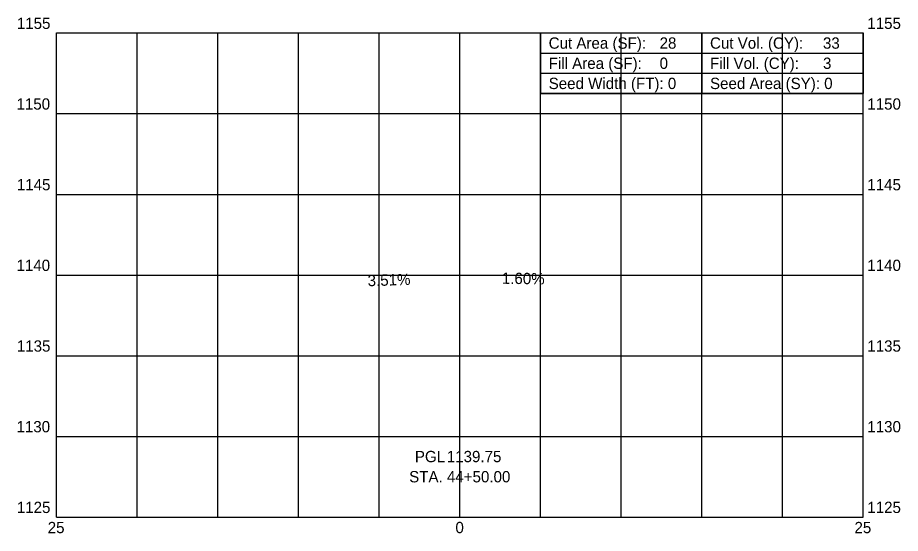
# Model space of a CAD drawing. Extents: x -27.4 to 27.3, y 1124 to 1156.
import ezdxf

# ---------------------------------------------------------------- set-up
doc = ezdxf.new("R2010")
doc.units = 0
for name, color, linetype in [('Default', 7, 'Continuous'), ('SH_Data', 7, 'Continuous'), ('SH_Major_Grid_Line', 7, 'Continuous'), ('SH_Masking', 7, 'Continuous'), ('SH_Text', 7, 'Continuous')]:
    doc.layers.add(name, color=color, linetype=linetype)

msp = doc.modelspace()

# ---------------------------------------------------------------- linework, layer by layer
at = {"layer": 'Default'}
msp.add_circle((25, 1155), 0.000417, dxfattribs=at)
msp.add_circle((25, 1155), 0.000417, dxfattribs=at)
msp.add_circle((25, 1155), 0.000417, dxfattribs=at)
msp.add_circle((25, 1155), 0.000417, dxfattribs=at)
msp.add_circle((25, 1155), 0.000417, dxfattribs=at)
msp.add_circle((25, 1155), 0.000417, dxfattribs=at)
msp.add_circle((25, 1155), 0.000417, dxfattribs=at)
msp.add_circle((25, 1155), 0.000417, dxfattribs=at)
msp.add_circle((25, 1155), 0.000417, dxfattribs=at)
msp.add_circle((25, 1155), 0.000417, dxfattribs=at)
msp.add_circle((25, 1155), 0.000417, dxfattribs=at)
msp.add_circle((25, 1155), 0.000417, dxfattribs=at)
at = {"layer": 'SH_Data'}
for p, q in [((5, 1155), (25, 1155)), ((5, 1155), (5, 1152.5)), ((15, 1155), (15, 1151.25)), ((25, 1155), (25, 1152.5)), ((5, 1153.75), (25, 1153.75)), ((5, 1152.5), (25, 1152.5)), ((13.298, 1151.875), (13.298, 1151.875)), ((22.946, 1151.875), (22.946, 1151.875))]:
    msp.add_line(p, q, dxfattribs=at)
msp.add_lwpolyline([(5, 1152.5), (5, 1151.25), (25, 1151.25), (25, 1152.5)], dxfattribs=at)
at = {"layer": 'SH_Major_Grid_Line'}
for p, q in [((-25, 1125), (-25, 1155)), ((-25, 1155), (25, 1155)), ((-20, 1125), (-20, 1155)), ((-15, 1125), (-15, 1155)), ((-10, 1125), (-10, 1155)), ((-5, 1125), (-5, 1155)), ((0, 1125), (0, 1155)), ((5, 1125), (5, 1155)), ((10, 1125), (10, 1155)), ((15, 1125), (15, 1155)), ((20, 1125), (20, 1155)), ((25, 1125), (25, 1155)), ((-25, 1150), (25, 1150)), ((-25, 1145), (25, 1145)), ((-25, 1140), (25, 1140)), ((-25, 1135), (25, 1135)), ((-25, 1130), (25, 1130)), ((-25, 1125), (25, 1125))]:
    msp.add_line(p, q, dxfattribs=at)
at = {"layer": 'SH_Masking'}
msp.add_lwpolyline([(5, 1155), (25, 1155), (25, 1151.25), (5, 1151.25)], close=True, dxfattribs=at)

# ---------------------------------------------------------------- texts
at = {"layer": 'SH_Text'}
for s, p in [('1155', (-27.461, 1155.25)), ('1155', (25.25, 1155.25)), ('Cut Area (SF):', (5.5, 1154.025)), ('28', (12.375, 1154.025)), ('Cut Vol. (CY):', (15.5, 1154.025)), ('33', (22.5, 1154.025)), ('Fill Area (SF):', (5.5, 1152.775)), ('0', (12.375, 1152.775)), ('Fill Vol. (CY):', (15.5, 1152.775)), ('3', (22.5, 1152.775)), ('Seed Width (FT): 0', (5.5, 1151.525)), ('Seed Area (SY): 0', (15.5, 1151.525)), ('1150', (-27.482, 1150.25)), ('1150', (25.25, 1150.25)), ('1145', (-27.461, 1145.25)), ('1145', (25.25, 1145.25)), ('1140', (-27.482, 1140.25)), ('1140', (25.25, 1140.25)), ('1135', (-27.461, 1135.25)), ('1135', (25.25, 1135.25)), ('1130', (-27.482, 1130.25)), ('1130', (25.25, 1130.25)), ('PGL ', (-2.793, 1128.4)), ('1139.75', (-0.814, 1128.4)), ('STA. 44+50.00', (-3.146, 1127.15)), ('1125', (-27.461, 1125.25)), ('1125', (25.25, 1125.25)), ('25', (-25.547, 1124)), ('0', (-0.278, 1124)), ('25', (24.453, 1124))]:
    msp.add_text(s, height=0.7, dxfattribs=at).set_placement(p)
for s, rotation, p in [('1.60%', 359.0833, (2.592, 1139.458)), ('3.51%', 2.01, (-5.709, 1139.299))]:
    msp.add_text(s, height=0.7, rotation=rotation, dxfattribs=at).set_placement(p)

doc.saveas('drawing.dxf')
